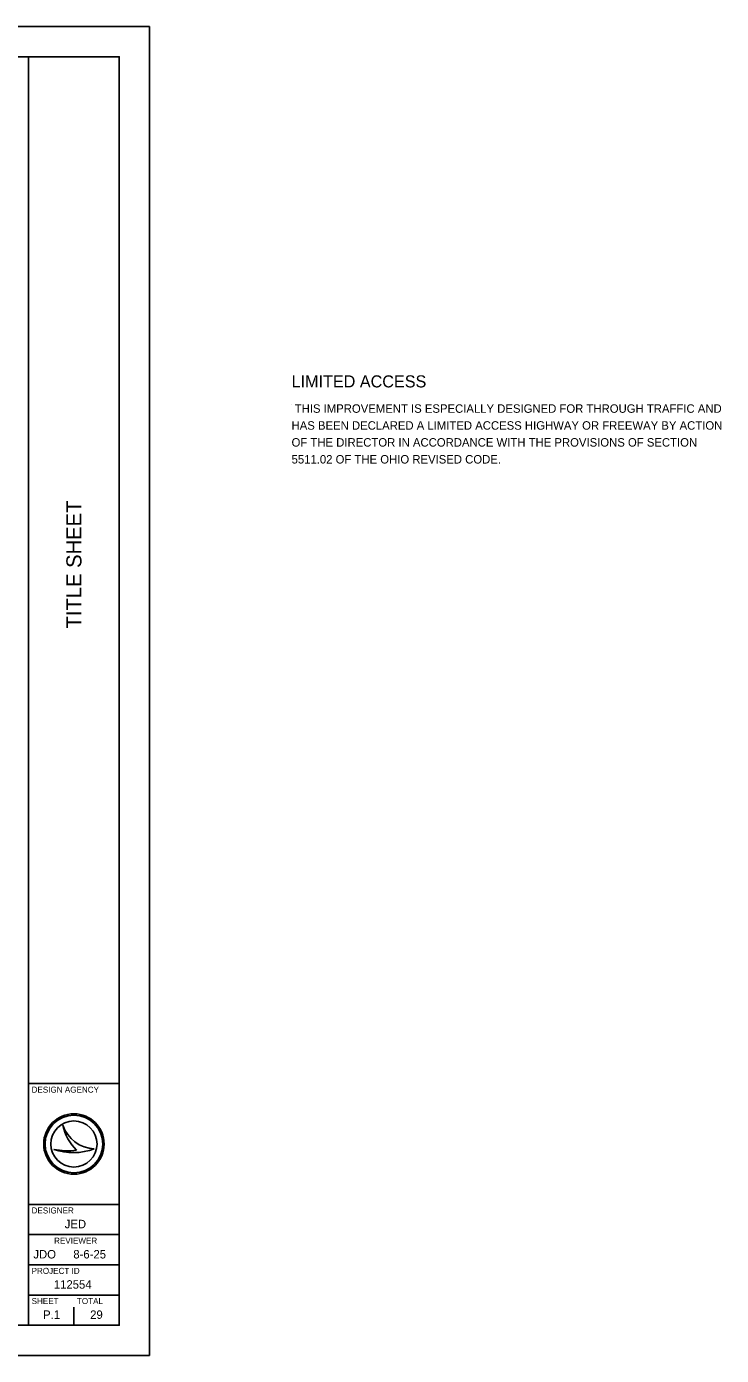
# Model space of a CAD drawing. Extents: x -11.1 to 43.5, y 0 to 22.
# Drawn here: x 31.97 to 43.46, y 0 to 22 of the extents above; entities that cross this region are included whole.
import ezdxf

# ---------------------------------------------------------------- set-up
doc = ezdxf.new("R2010")
doc.units = 0
for name, color, linetype in [('SH_Border', 7, 'Continuous'), ('SH_Cut_Line', 7, 'Continuous'), ('SH_Data', 7, 'Continuous'), ('SH_Text', 7, 'Continuous')]:
    doc.layers.add(name, color=color, linetype=linetype)

msp = doc.modelspace()

# ---------------------------------------------------------------- linework, layer by layer
at = {"layer": 'SH_Border'}
for p, q in [((32, 0.5), (32, 21.5)), ((32, 4.5), (33.5, 4.5)), ((32, 2.5), (33.5, 2.5)), ((32, 2), (33.5, 2)), ((32, 1.5), (33.5, 1.5)), ((32, 1), (33.5, 1))]:
    msp.add_line(p, q, dxfattribs=at)
msp.add_lwpolyline([(1.5, 21.5), (33.5, 21.5), (33.5, 0.5), (1.5, 0.5)], close=True, dxfattribs=at)
at = {"layer": 'SH_Cut_Line'}
msp.add_lwpolyline([(0, 0), (34, 0), (34, 22), (0, 22)], close=True, dxfattribs=at)
at = {"layer": 'SH_Data'}
for p, q in [((36.35, 15.746), (36.35, 15.746)), ((32.567, 3.81), (32.567, 3.81)), ((32.417, 3.41), (32.417, 3.41)), ((32.75, 3.5), (32.75, 3.5)), ((33.087, 3.419), (33.087, 3.419)), ((32.375, 0.675), (32.375, 0.675)), ((32.75, 0.5), (32.75, 0.8))]:
    msp.add_line(p, q, dxfattribs=at)
for radius in [0.5, 0.477, 0.477, 0.382]:
    msp.add_circle((32.75, 3.5), radius, dxfattribs=at)
for centre, radius, start, end in [((33.116, 3.998), 0.58, 198.9257, 198.9319), ((33.347, 3.97), 0.796, 191.6379, 191.6421), ((33.116, 3.998), 0.58, 198.9319, 267.1657), ((33.347, 3.97), 0.796, 191.6421, 226.0947), ((32.739, 4.37), 1.013, 251.4576, 290.0832), ((32.648, 4.654), 1.266, 259.4964, 259.4995), ((32.739, 4.37), 1.013, 251.4527, 251.4576), ((32.648, 4.654), 1.266, 259.4995, 276.6672)]:
    msp.add_arc(centre, radius, start, end, dxfattribs=at)

# ---------------------------------------------------------------- texts
msp.add_text('TITLE SHEET', height=0.25, rotation=90, dxfattribs=at).set_placement((32.875, 12.035))
for s, height, p in [('DESIGN AGENCY', 0.1, (32.05, 4.35)), ('DESIGNER', 0.1, (32.05, 2.35)), ('JED', 0.14, (32.598, 2.105)), ('REVIEWER', 0.1, (32.422, 1.85)), ('JDO', 0.14, (32.079, 1.605)), ('8-6-25', 0.14, (32.74, 1.605)), ('PROJECT ID', 0.1, (32.05, 1.35)), ('112554', 0.14, (32.418, 1.105)), ('SHEET', 0.1, (32.05, 0.85)), ('TOTAL', 0.1, (32.8, 0.85)), ('P.1', 0.14, (32.24, 0.605)), ('29', 0.14, (33.019, 0.605))]:
    msp.add_text(s, height=height, dxfattribs=at).set_placement(p)
at = {"layer": 'SH_Text'}
for s, height, p in [('LIMITED ACCESS', 0.2, (36.35, 16.026)), (' THIS IMPROVEMENT IS ESPECIALLY DESIGNED FOR THROUGH TRAFFIC AND', 0.14, (36.35, 15.606)), ('HAS BEEN DECLARED A LIMITED ACCESS HIGHWAY OR FREEWAY BY ACTION', 0.14, (36.35, 15.326)), ('OF THE DIRECTOR IN ACCORDANCE WITH THE PROVISIONS OF SECTION', 0.14, (36.35, 15.046)), ('5511.02 OF THE OHIO REVISED CODE.', 0.14, (36.35, 14.766))]:
    msp.add_text(s, height=height, dxfattribs=at).set_placement(p)

doc.saveas('drawing.dxf')
